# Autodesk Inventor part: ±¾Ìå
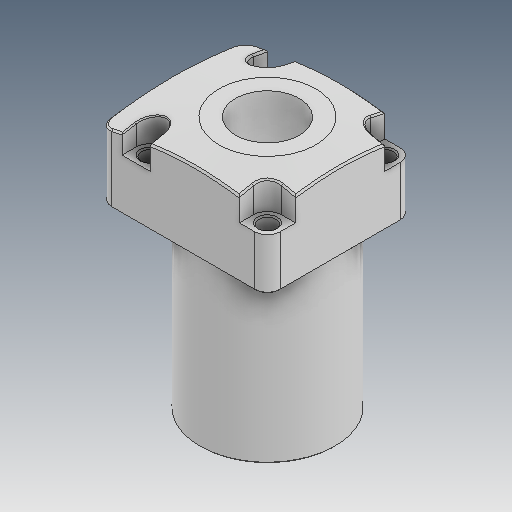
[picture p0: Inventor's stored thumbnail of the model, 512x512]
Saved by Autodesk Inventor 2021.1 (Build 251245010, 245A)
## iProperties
Created: 2019-04
Part Number: ±¾Ìå
Material: Ogólny
Document SubType Name: Modeling
Designer: user
Density: 1 g/cm^3
Appearance: Domyślna
Author: user
Revision Number: ÈÎºÎ
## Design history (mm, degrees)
feature "ÇÐ³ý-É¨Ãè2"
node "Bryła1"
